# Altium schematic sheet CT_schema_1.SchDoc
size 454 x 258 mm
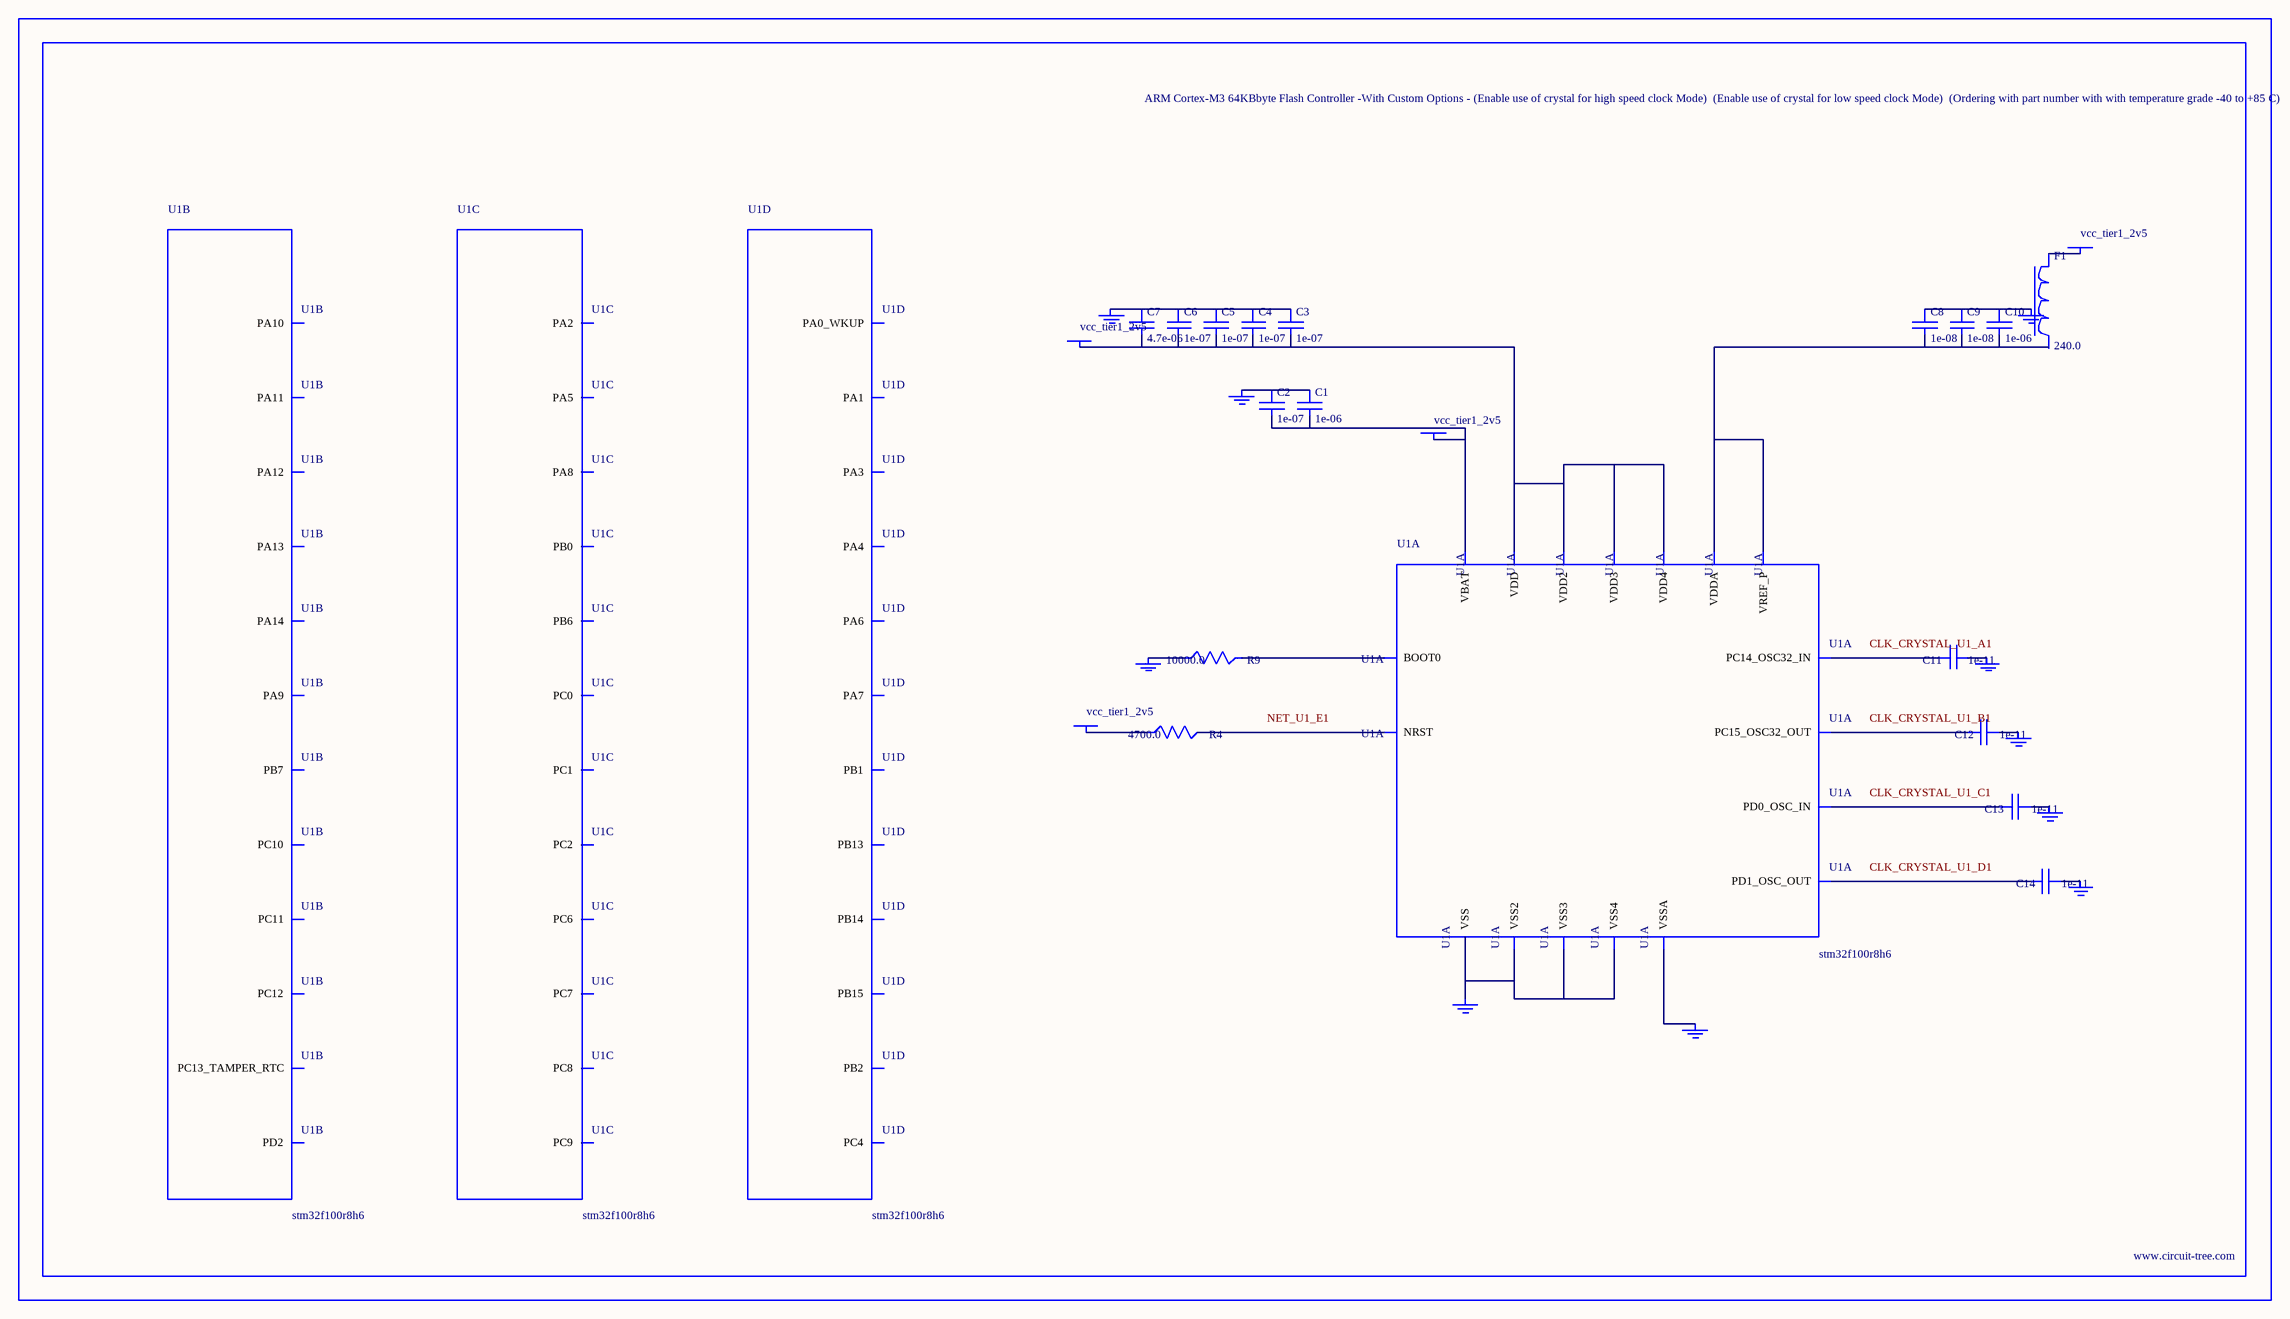
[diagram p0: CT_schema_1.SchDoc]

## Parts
BORDER0  (no value)
C1  1e-06  [C0603]
C2  1e-07  [C0603]
C3  1e-07  [C0603]
C4  1e-07  [C0603]
C5  1e-07  [C0603]
C6  1e-07  [C0603]
C7  4.7e-06  [C0603]
C8  1e-08  [C0603]
C9  1e-08  [C0603]
C10  1e-06  [C0603]
C11  1e-11  [C0402]
C12  1e-11  [C0402]
C13  1e-11  [C0402]
C14  1e-11  [C0402]
F1  240.0  [L0603]
GND_INSTANCE_0_0  (no value)
GND_INSTANCE_0_1  (no value)
GND_INSTANCE_0_2  (no value)
GND_INSTANCE_0_3  (no value)
GND_INSTANCE_0_4  (no value)
GND_INSTANCE_0_5  (no value)
GND_INSTANCE_0_6  (no value)
GND_INSTANCE_0_7  (no value)
GND_INSTANCE_0_8  (no value)
GND_INSTANCE_0_9  (no value)
POWER_INSTANCE_0_0  vcc_tier1_2v5
POWER_INSTANCE_0_1  vcc_tier1_2v5
POWER_INSTANCE_0_2  vcc_tier1_2v5
POWER_INSTANCE_0_3  vcc_tier1_2v5
R4  4700.0  [R0603]
R9  10000.0  [R0603]
U1  stm32f100r8h6  [TFBGA64]  (parts A,B,C,D of 7)

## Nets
NetC1_1: C1.1 C2.1 GND_INSTANCE_0_0.0(GND)
NetC1_2: C1.2 C2.2 POWER_INSTANCE_0_0.0(PWR) U1.B2(VBAT)
NetC3_1: C3.1 C4.1 C5.1 C6.1 C7.1 GND_INSTANCE_0_2.0(GND)
NetC3_2: C3.2 C4.2 C5.2 C6.2 C7.2 POWER_INSTANCE_0_2.0(PWR) U1.D2(VDD) U1.E4(VDD2) U1.E5(VDD3) U1.E6(VDD4)
NetC8_1: C8.1 C9.1 C10.1 GND_INSTANCE_0_1.0(GND)
NetC8_2: C8.2 C9.2 C10.2 U1.G1(VREF_P) U1.H1(VDDA)
NetC11_1: C11.1 GND_INSTANCE_0_4.0(GND)
NetC11_2: C11.2 U1.A1(PC14_OSC32_IN)
NetC12_1: C12.1 GND_INSTANCE_0_5.0(GND)
NetC12_2: C12.2 U1.B1(PC15_OSC32_OUT)
NetC13_1: C13.1 GND_INSTANCE_0_6.0(GND)
NetC13_2: C13.2 U1.C1(PD0_OSC_IN)
NetC14_1: C14.1 GND_INSTANCE_0_7.0(GND)
NetC14_2: C14.2 U1.D1(PD1_OSC_OUT)
NetF1_1: F1.1 POWER_INSTANCE_0_1.0(PWR)
NetGND_INSTANCE_0_3_0: GND_INSTANCE_0_3.0(GND) R9.1
NetGND_INSTANCE_0_8_0: GND_INSTANCE_0_8.0(GND) U1.F1(VSSA)
NetGND_INSTANCE_0_9_0: GND_INSTANCE_0_9.0(GND) U1.C2(VSS) U1.D4(VSS2) U1.D5(VSS3) U1.D6(VSS4)
NetPOWER_INSTANCE_0_3_0: POWER_INSTANCE_0_3.0(PWR) R4.1
NetR4_2: R4.2 U1.E1(NRST)
NetR9_2: R9.2 U1.B4(BOOT0)

Not connected (* = marked no-connect by the designer): F1 2; U1 A2(PC13_TAMPER_RTC) A7(PA14) A8(PA13) B5(PD2) B6(PC11) B7(PC10) B8(PA12) C3(PB7) C5(PC12) C6(PA10) C7(PA9) C8(PA11) D3(PB6) D7(PA8) D8(PC9) E2(PC1) E3(PC0) E7(PC7) E8(PC8) F2(PC2) F3(PA2) F4(PA5) F5(PB0) F6(PC6) F7(PB15) F8(PB14) G2(PA0_WKUP) G3(PA3) G4(PA6) G5(PB1) G6(PB2) G8(PB13) H2(PA1) H3(PA4) H4(PA7) H5(PC4)

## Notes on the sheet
- Labels drawn without touching a wire or pin: CLK_CRYSTAL_U1_A1, CLK_CRYSTAL_U1_B1, CLK_CRYSTAL_U1_C1, CLK_CRYSTAL_U1_D1, NET_U1_E1

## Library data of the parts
BORDER0 = BORDER_PAGE0
C1 C10 = C0603C105K3RACTU
C2-C6 = 06035C104K4Z2A
C7 = GRM188R6YA475KE15D
C8 C9 = 06035C103K4Z2A
C11-C14 = C0402C100K3GACTU
F1 = Z0603C241ASMST
GND_INSTANCE_0_0-GND_INSTANCE_0_9 = GND
POWER_INSTANCE_0_0-POWER_INSTANCE_0_3 = PWR
R4 = RC0603JR-074K7L
R9 = RC0603JR-0710KL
